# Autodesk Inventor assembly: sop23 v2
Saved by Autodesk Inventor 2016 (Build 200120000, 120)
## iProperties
Created: 2016-09
Part Number: sop23 v2
Document SubType Name: Assembly
Designer: Administrator
Author: Administrator
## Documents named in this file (3)
- c:\worker\convert-fusion-aug-2016\tmp\job-1\19\output\files\b1646d38-3d95-4128-a552-c87d2d1b62c9\sop23 v2.iam
- c:\worker\convert-fusion-aug-2016\tmp\job-1\19\output\files\b1646d38-3d95-4128-a552-c87d2d1b62c9\package.ipt
- c:\worker\convert-fusion-aug-2016\tmp\job-1\19\output\files\b1646d38-3d95-4128-a552-c87d2d1b62c9\lead (1).ipt
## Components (2 placed, 2 different names)
1. package:1
2. lead (1):1
